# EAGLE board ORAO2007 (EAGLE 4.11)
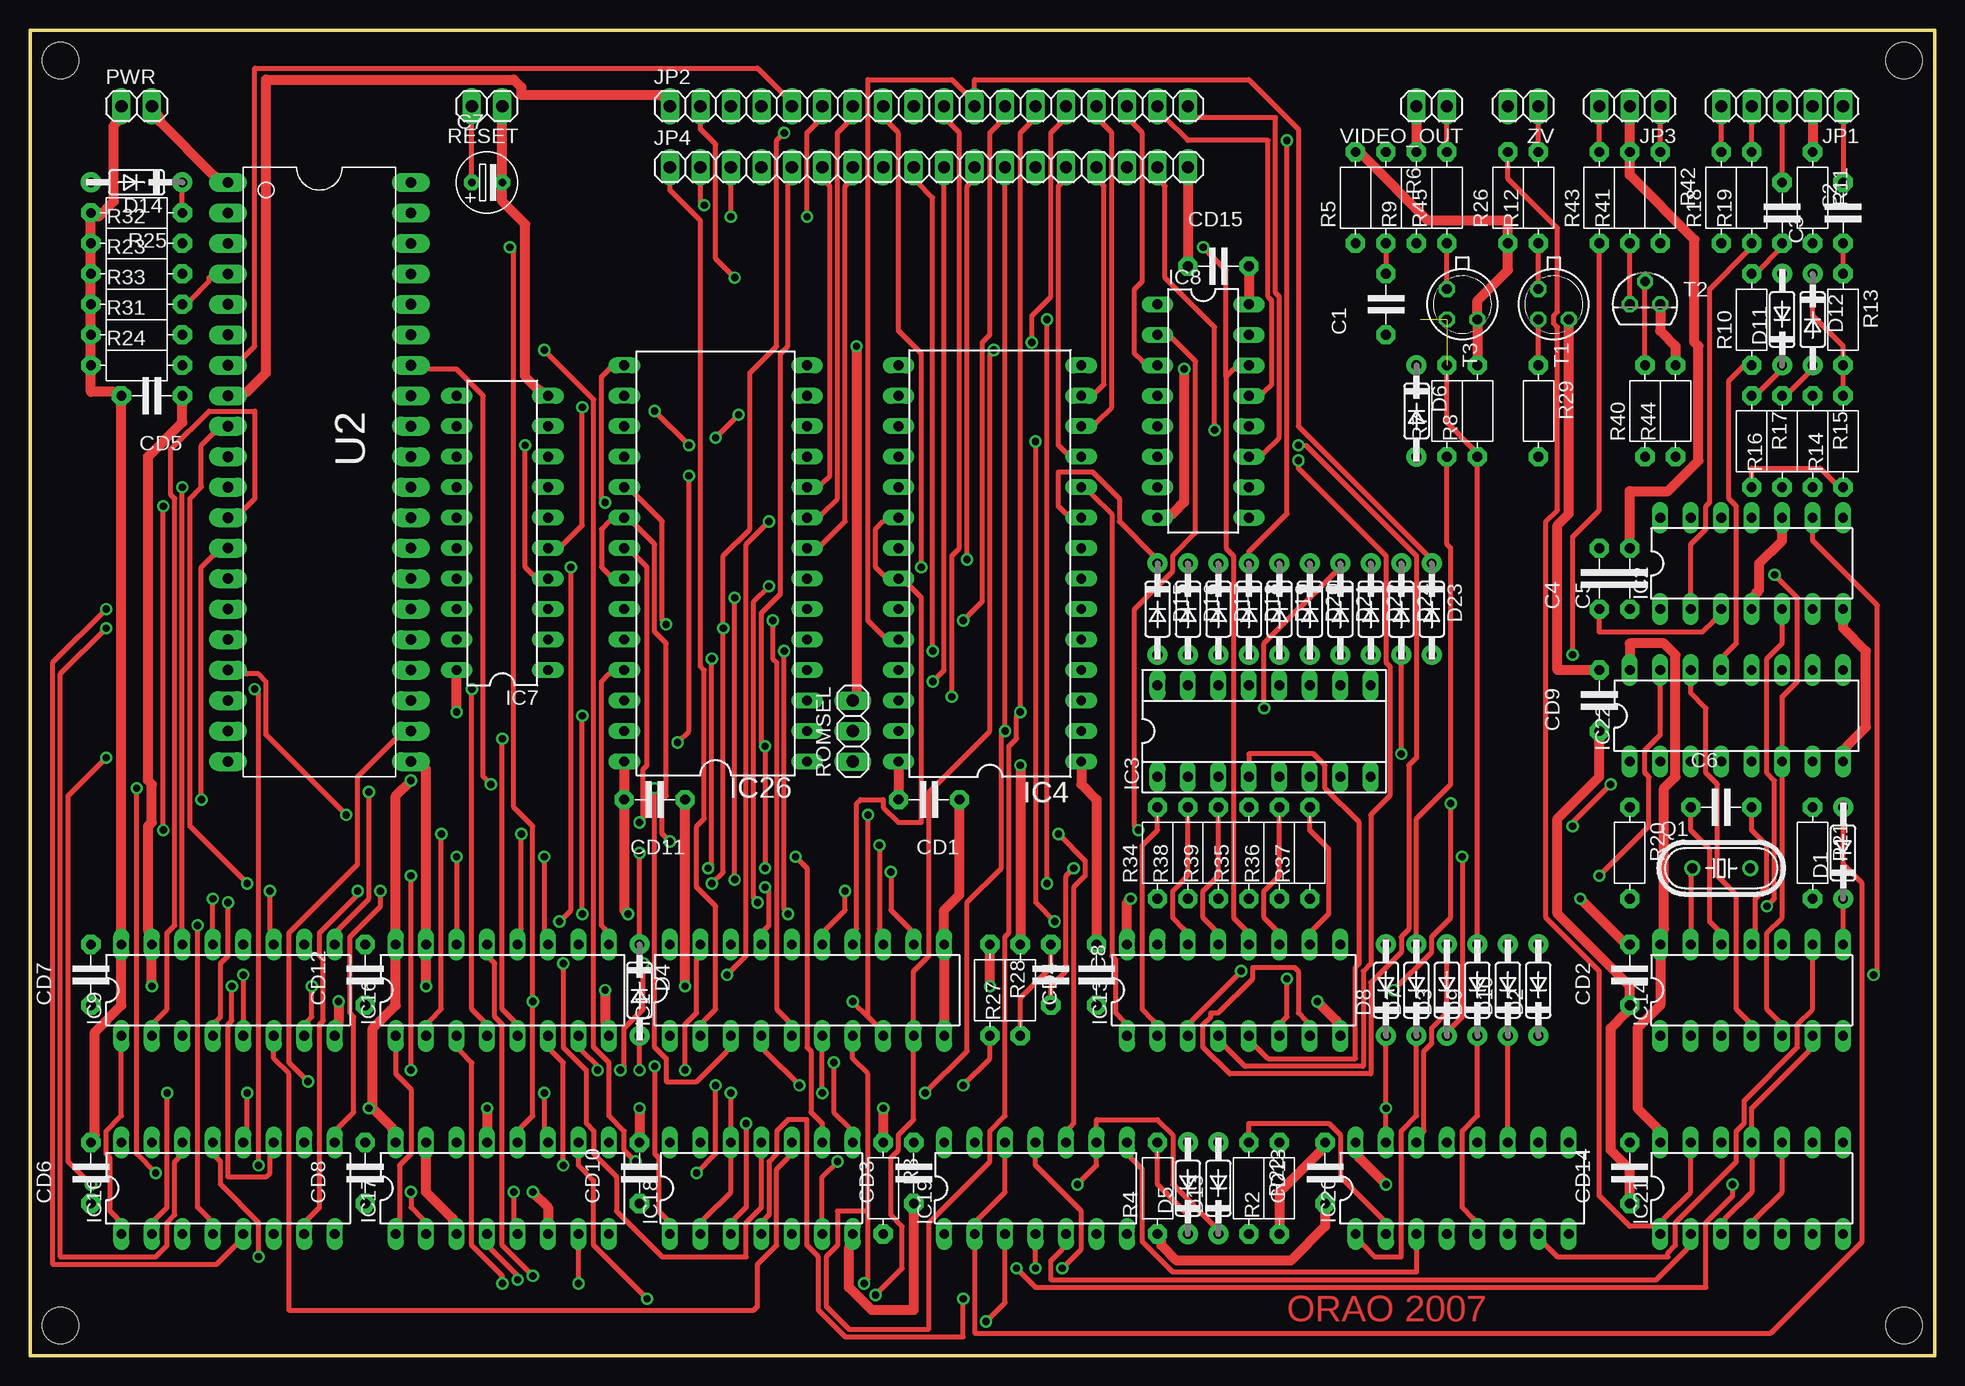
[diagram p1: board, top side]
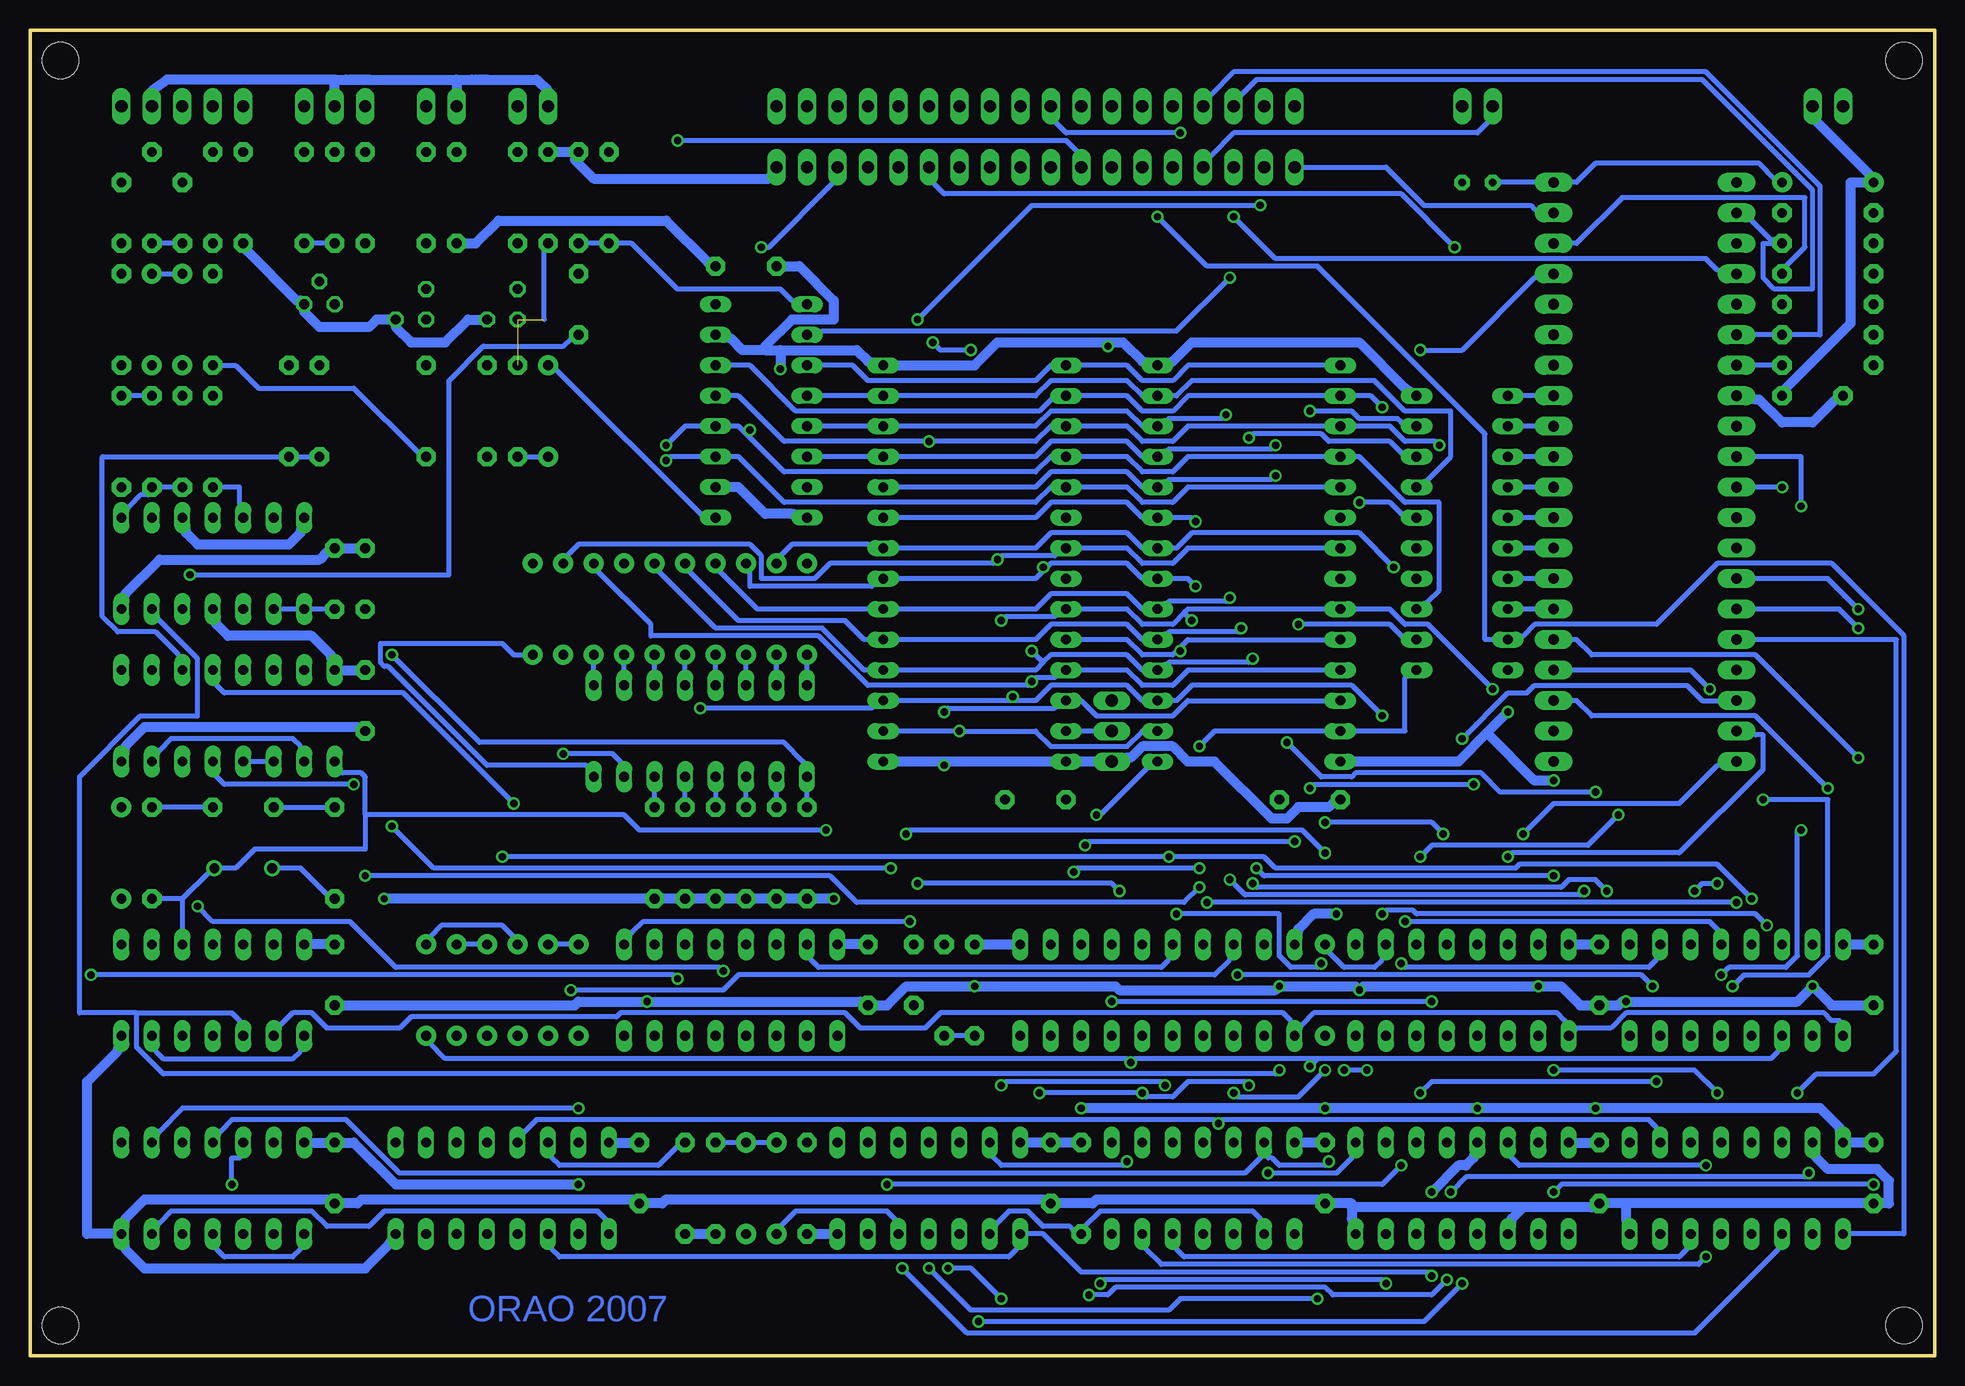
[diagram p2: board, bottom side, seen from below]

Size 158.75 x 110.49 mm. Coordinates in mm from the lower left corner, seen from the top.
Outline: 0,0 158.75,0 158.75,110.49 0,110.49 0,0
Copper layers (1*16): Top 0.035mm / dielectric 1.5mm / Bottom 0.035mm
Design rules "default": minimum track width 16mil, minimum drill 24mil, track to track 8mil, track to pad 8mil, pad to pad 8mil, via to via 8mil, smd to smd 8mil, copper to edge 40mil, drill to drill 8mil, minimum pad ring 10mil, minimum via ring 8mil, stop-mask expansion 4mil, vias tented up to drill 0mil, thermal gap 10mil
Net classes: 0 default: width 0.406 mm, drill 0.203 mm; 1 gnd: width 0.813 mm, drill 0.203 mm; 2 vcc: width 0.813 mm, drill 0.203 mm
Holes 3.05 mm at 2.54,107.95 156.21,107.95 156.21,2.54 2.54,2.54

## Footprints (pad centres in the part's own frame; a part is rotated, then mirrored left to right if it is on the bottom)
C-5 = drill 0.813 pad 1.6 octagon: 1 -2.54,0; 2 2.54,0
ES-2,5L = drill 0.61 pad 1.27 octagon: 1 0,0; 2 2.54,0
DO35-10 = drill 0.813 pad 1.676 round: A 3.81,0; C -3.81,0
DIL20 = drill 0.813 long: 1 -11.43,-3.81; 2 -8.89,-3.81; 3 -6.35,-3.81; 4 -3.81,-3.81; 5 -1.27,-3.81; 6 1.27,-3.81; 7 3.81,-3.81; 8 6.35,-3.81; 9 8.89,-3.81; 10 11.43,-3.81; 11 11.43,3.81; 12 8.89,3.81; 13 6.35,3.81; 14 3.81,3.81; 15 1.27,3.81; 16 -1.27,3.81; 17 -3.81,3.81; 18 -6.35,3.81; 19 -8.89,3.81; 20 -11.43,3.81
DIL14 = drill 0.813 long: 1 -7.62,-3.81; 2 -5.08,-3.81; 3 -2.54,-3.81; 4 0,-3.81; 5 2.54,-3.81; 6 5.08,-3.81; 7 7.62,-3.81; 8 7.62,3.81; 9 5.08,3.81; 10 2.54,3.81; 11 0,3.81; 12 -2.54,3.81; 13 -5.08,3.81; 14 -7.62,3.81
SOCKED-16 = drill 0.813 long: 1 -8.89,-3.81; 2 -6.35,-3.81; 3 -3.81,-3.81; 4 -1.27,-3.81; 5 1.27,-3.81; 6 3.81,-3.81; 7 6.35,-3.81; 8 8.89,-3.81; 9 8.89,3.81; 10 6.35,3.81; 11 3.81,3.81; 12 1.27,3.81; 13 -1.27,3.81; 14 -3.81,3.81; 15 -6.35,3.81; 16 -8.89,3.81
DIL28 = drill 0.813 long: 1 -16.51,-7.62; 2 -13.97,-7.62; 3 -11.43,-7.62; 4 -8.89,-7.62; 5 -6.35,-7.62; 6 -3.81,-7.62; 7 -1.27,-7.62; 8 1.27,-7.62; 9 3.81,-7.62; 10 6.35,-7.62; 11 8.89,-7.62; 12 11.43,-7.62; 13 13.97,-7.62; 14 16.51,-7.62; 15 16.51,7.62; 16 13.97,7.62; 17 11.43,7.62; 18 8.89,7.62; 19 6.35,7.62; 20 3.81,7.62; 21 1.27,7.62; 22 -1.27,7.62; 23 -3.81,7.62; 24 -6.35,7.62; 25 -8.89,7.62; 26 -11.43,7.62; 27 -13.97,7.62; 28 -16.51,7.62
DIL16 = drill 0.813 long: 1 -8.89,-3.81; 2 -6.35,-3.81; 3 -3.81,-3.81; 4 -1.27,-3.81; 5 1.27,-3.81; 6 3.81,-3.81; 7 6.35,-3.81; 8 8.89,-3.81; 9 8.89,3.81; 10 6.35,3.81; 11 3.81,3.81; 12 1.27,3.81; 13 -1.27,3.81; 14 -3.81,3.81; 15 -6.35,3.81; 16 -8.89,3.81
DIL28-6 = drill 0.813 long: 1 -16.51,-7.62; 2 -13.97,-7.62; 3 -11.43,-7.62; 4 -8.89,-7.62; 5 -6.35,-7.62; 6 -3.81,-7.62; 7 -1.27,-7.62; 8 1.27,-7.62; 9 3.81,-7.62; 10 6.35,-7.62; 11 8.89,-7.62; 12 11.43,-7.62; 13 13.97,-7.62; 14 16.51,-7.62; 15 16.51,7.62; 16 13.97,7.62; 17 11.43,7.62; 18 8.89,7.62; 19 6.35,7.62; 20 3.81,7.62; 21 1.27,7.62; 22 -1.27,7.62; 23 -3.81,7.62; 24 -6.35,7.62; 25 -8.89,7.62; 26 -11.43,7.62; 27 -13.97,7.62; 28 -16.51,7.62
1X05 = drill 1.016 long: 1 -5.08,0; 2 -2.54,0; 3 0,0; 4 2.54,0; 5 5.08,0
1X18 = drill 1.016 long: 1 -21.59,0; 2 -19.05,0; 3 -16.51,0; 4 -13.97,0; 5 -11.43,0; 6 -8.89,0; 7 -6.35,0; 8 -3.81,0; 9 -1.27,0; 10 1.27,0; 11 3.81,0; 12 6.35,0; 13 8.89,0; 14 11.43,0; 15 13.97,0; 16 16.51,0; 17 19.05,0; 18 21.59,0
1X03 = drill 1.016 long: 1 -2.54,0; 2 0,0; 3 2.54,0
1X02 = drill 1.016 long: 1 -1.27,0; 2 1.27,0
HC49/S = drill 0.813 round: 1 -2.413,0; 2 2.413,0
R-7,5 = drill 0.813 pad 1.6 octagon: 1 -3.81,0; 2 3.81,0
TO18 = drill 0.813 octagon: 1 -1.27,-1.27; 2 1.27,-1.27; 3 1.27,1.27
TO92 = drill 0.813 octagon: 1 1.27,0; 2 0,1.905; 3 -1.27,0
DIP-40 = drill 0.889 pad 1.6 long: 1 -22.86,-7.62; 2 -20.32,-7.62; 3 -17.78,-7.62; 4 -15.24,-7.62; 5 -12.7,-7.62; 6 -10.16,-7.62; 7 -7.62,-7.62; 8 -5.08,-7.62; 9 -2.54,-7.62; 10 0,-7.62; 11 2.54,-7.62; 12 5.08,-7.62; 13 7.62,-7.62; 14 10.16,-7.62; 15 12.7,-7.62; 16 15.24,-7.62; 17 17.78,-7.62; 18 20.32,-7.62; 19 22.86,-7.62; 20 25.4,-7.62; 21 25.4,7.62; 22 22.86,7.62; 23 20.32,7.62; 24 17.78,7.62; 25 15.24,7.62; 26 12.7,7.62; 27 10.16,7.62; 28 7.62,7.62; 29 5.08,7.62; 30 2.54,7.62; 31 0,7.62; 32 -2.54,7.62; 33 -5.08,7.62; 34 -7.62,7.62; 35 -10.16,7.62; 36 -12.7,7.62; 37 -15.24,7.62; 38 -17.78,7.62; 39 -20.32,7.62; 40 -22.86,7.62

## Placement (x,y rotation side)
C1  100p  [C-5]  113.03,87.63 90 top
C2  [C-5]  146.05,95.25 270 top
C3  100n  [C-5]  151.13,95.25 90 top
C4  22n  [C-5]  130.81,64.77 90 top
C5  10n  [C-5]  133.35,64.77 90 top
C6  1n  [C-5]  140.97,45.72 0 top
C7  10u  [ES-2,5L]  36.83,97.79 0 top
C8  100p  [C-5]  85.09,31.75 270 top
CD1  100n  [C-5]  74.93,46.35 180 top
CD2  100n  [C-5]  133.35,31.75 90 top
CD3  100n  [C-5]  73.66,15.24 90 top
CD4  100n  [C-5]  88.9,31.75 90 top
CD5  100n  [C-5]  10.16,80.01 180 top
CD6  100n  [C-5]  5.08,15.24 90 top
CD7  100n  [C-5]  5.08,31.75 90 top
CD8  100n  [C-5]  27.94,15.24 90 top
CD9  100n  [C-5]  130.81,54.61 90 top
CD10  100n  [C-5]  50.8,15.24 90 top
CD11  100n  [C-5]  52.07,46.35 180 top
CD12  100n  [C-5]  27.94,31.75 90 top
CD13  100n  [C-5]  107.95,15.24 90 top
CD14  100n  [C-5]  133.35,15.24 90 top
CD15  100n  [C-5]  99.06,90.81 0 top
D1  1N4148  [DO35-10]  151.13,41.91 90 top
D2  1N4148  [DO35-10]  125.73,30.48 90 top
D3  1N4148  [DO35-10]  118.11,30.48 90 top
D4  1N4148  [DO35-10]  50.8,30.48 270 top
D5  1N4148  [DO35-10]  96.52,13.97 90 top
D6  1N4148  [DO35-10]  115.57,78.74 270 top
D7  1N4148  [DO35-10]  115.57,30.48 90 top
D8  1N4148  [DO35-10]  113.03,30.48 90 top
D9  1N4148  [DO35-10]  120.65,30.48 90 top
D10  1N4148  [DO35-10]  123.19,30.48 90 top
D11  1N4148  [DO35-10]  146.05,86.36 90 top
D12  1N4148  [DO35-10]  148.59,86.36 270 top
D13  1N4148  [DO35-10]  99.06,13.97 90 top
D14  1N4148  [DO35-10]  8.89,97.79 180 top
D15  1N4148  [DO35-10]  93.98,62.23 270 top
D16  1N4148  [DO35-10]  96.52,62.23 270 top
D17  1N4148  [DO35-10]  99.06,62.23 270 top
D18  1N4148  [DO35-10]  101.6,62.23 270 top
D19  1N4148  [DO35-10]  104.14,62.23 270 top
D20  1N4148  [DO35-10]  106.68,62.23 270 top
D21  1N4148  [DO35-10]  109.22,62.23 270 top
D22  1N4148  [DO35-10]  111.76,62.23 270 top
D23  1N4148  [DO35-10]  116.84,62.23 270 top
D24  1N4148  [DO35-10]  114.3,62.23 270 top
IC1  GAL16V8  [DIL20]  64.77,30.48 0 top
IC2  NE556N  [DIL14]  143.51,66.04 0 top
IC3  [SOCKED-16]  102.87,52.07 0 top
IC4  27256  [DIL28]  80.01,66.04 90 top
IC7  74AC245N  [DIL20]  39.37,68.58 90 top
IC8  74HC165N  [DIL16]  97.79,78.74 270 top
IC9  74AC257N  [DIL16]  16.51,30.48 0 top
IC10  74AC257N  [DIL16]  16.51,13.97 0 top
IC13  74AC257N  [DIL16]  100.33,30.48 0 top
IC14  74AC04N  [DIL14]  143.51,30.48 0 top
IC16  74AC257N  [DIL16]  39.37,30.48 0 top
IC17  74AC257N  [DIL16]  39.37,13.97 0 top
IC18  74AC393N  [DIL14]  60.96,13.97 0 top
IC19  74AC393N  [DIL14]  83.82,13.97 0 top
IC20  74AC139N  [DIL16]  119.38,13.97 0 top
IC21  74AC74N  [DIL14]  143.51,13.97 0 top
IC22  74AC390N  [DIL16]  142.24,53.34 0 top
IC26  [DIL28-6]  57.15,66.04 90 top
JP1  [1X05]  146.05,104.14 180 top
JP2  [1X18]  74.93,104.14 0 top
JP3  [1X03]  133.35,104.14 180 top
JP4  [1X18]  74.93,99.06 0 top
PWR  [1X02]  8.89,104.14 0 top
Q1  8MHz  [HC49/S]  140.97,40.64 0 top
R2  10K  [R-7,5]  104.14,13.97 90 top
R3  10K  [R-7,5]  71.12,13.97 270 top
R4  470  [R-7,5]  93.98,13.97 90 top
R5  1K  [R-7,5]  110.49,96.52 90 top
R6  1K5  [R-7,5]  113.03,96.52 270 top
R7  330  [R-7,5]  118.11,78.74 90 top
R8  1K  [R-7,5]  120.65,78.74 90 top
R9  4K7  [R-7,5]  115.57,96.52 90 top
R10  47K  [R-7,5]  143.51,86.36 90 top
R11  470  [R-7,5]  148.59,96.52 270 top
R12  47  [R-7,5]  125.73,96.52 90 top
R13  10K  [R-7,5]  151.13,86.36 270 top
R14  22K  [R-7,5]  151.13,76.2 90 top
R15  22K  [R-7,5]  148.59,76.2 270 top
R16  47K  [R-7,5]  146.05,76.2 90 top
R17  47K  [R-7,5]  143.51,76.2 270 top
R18  100  [R-7,5]  140.97,96.52 90 top
R19  100  [R-7,5]  143.51,96.52 90 top
R20  330  [R-7,5]  133.35,41.91 270 top
R21  330  [R-7,5]  148.59,41.91 270 top
R22  10K  [R-7,5]  101.6,13.97 270 top
R23  10K  [R-7,5]  8.89,90.17 0 top
R24  10K  [R-7,5]  8.89,82.55 0 top
R25  10K  [R-7,5]  8.89,95.25 180 top
R26  10K  [R-7,5]  123.19,96.52 90 top
R27  1K  [R-7,5]  82.55,30.48 90 top
R28  1K  [R-7,5]  80.01,30.48 270 top
R29  1K  [R-7,5]  125.73,78.74 270 top
R31  10K  [R-7,5]  8.89,85.09 0 top
R32  10K  [R-7,5]  8.89,92.71 0 top
R33  10K  [R-7,5]  8.89,87.63 0 top
R34  10K  [R-7,5]  93.98,41.91 90 top
R35  10K  [R-7,5]  101.6,41.91 90 top
R36  10K  [R-7,5]  104.14,41.91 90 top
R37  10K  [R-7,5]  106.68,41.91 90 top
R38  10K  [R-7,5]  96.52,41.91 90 top
R39  10K  [R-7,5]  99.06,41.91 90 top
R40  10K  [R-7,5]  134.62,78.74 90 top
R41  10K  [R-7,5]  133.35,96.52 90 top
R42  470  [R-7,5]  135.89,96.52 270 top
R43  1K2  [R-7,5]  130.81,96.52 90 top
R44  4K7  [R-7,5]  137.16,78.74 90 top
R45  47  [R-7,5]  118.11,96.52 90 top
RESET  [1X02]  38.1,104.14 180 top
ROMSEL  [1X03]  68.58,52.07 90 top
T1  BC108C  [TO18]  127,87.63 270 top
T2  BC214  [TO92]  134.62,87.63 0 top
T3  BC108C  [TO18]  119.38,87.63 270 top
U2  [DIP-40]  24.13,74.93 270 top
VIDEO_OUT  [1X02]  116.84,104.14 180 top
ZV  [1X02]  124.46,104.14 180 top

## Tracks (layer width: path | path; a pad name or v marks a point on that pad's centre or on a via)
1B9  (via drill 0.61)
  Top 0.406: v52.07,24.13 52.07,16.83 52.39,16.51 52.39,12.06 53.02,11.43 IC18.1 | v66.99,24.45 66.99,20.32 68.26,19.05 IC18.8
  Bottom 0.406: 51.44,24.77 v52.07,24.13 | 51.44,24.77 13.65,24.77 13.02,25.4 IC9.3 | 51.44,24.77 66.67,24.77 v66.99,24.45 67.31,24.77 124.14,24.77 125.41,26.04 D2.C
1B10  (via drill 0.61)
  Top 0.406: v86.04,7.3 87.63,8.89 87.63,12.06 83.82,15.88 IC19.11
  Bottom 0.406: v86.04,7.3 80.64,1.91 20,1.91 13.02,8.89 IC10.3
1B16  (via drill 0.61)
  Top 0.406: v39.37,6.03 39.37,6.67 36.83,9.21 36.83,24.45 35.88,25.4 IC16.3 | v79.69,2.86 81.28,4.45 IC19.3
  Bottom 0.406: v39.37,6.03 42.55,2.86 v79.69,2.86
2B10
  Bottom 0.406: IC10.6 20.64,8.89 21.27,8.26 62.55,8.26 63.18,8.89 IC18.5
2B16  (via drill 0.61)
  Top 0.406: v44.45,15.88 44.45,24.45 43.5,25.4 IC16.6 | v87.31,14.29 88.9,15.88 IC19.9 88.9,19.68 93.98,19.68 95.25,18.41 95.25,14.29 98.74,10.79 D13.C
  Bottom 0.406: v44.45,15.88 46.04,14.29 v87.31,14.29
2MHZ  (via drill 0.61)
  Top 0.406: v131.76,47.62 128.59,44.45 v128.59,44.13 | v87,40.64 86.36,40.01 86.36,32.07 85.09,30.8 C8.2
  Bottom 0.406: v131.76,47.62 142.56,47.62 143.19,48.26 IC22.5 | v128.59,44.13 125.09,40.64 v87,40.64
2MHZ'  (via drill 0.61)
  Top 0.406: v64.14,22.54 61.28,25.4 IC1.4 | v77.79,22.54 80.01,24.77 R28.2 | C8.1 85.09,32.38 82.55,29.84 R27.1
  Bottom 0.406: v64.14,22.54 64.45,22.86 77.47,22.86 v77.79,22.54 | R28.2 R27.1
2Y0
  Bottom 0.406: IC1.16 63.82,33.02 64.45,32.38 93.03,32.38 93.66,33.02 IC13.15
2Y1  (via drill 0.61)
  Top 0.406: v61.28,39.05 61.59,38.73 61.59,35.88 61.28,35.56 IC1.17 | v130.81,40.01 134.94,44.13 134.94,48.26 134.62,48.58 134.62,50.48 135.89,51.75 IC22.15
  Bottom 0.406: v61.28,39.05 62.55,37.78 89.85,37.78 92.08,40.01 v130.81,40.01
2Y2  (via drill 0.61)
  Top 0.406: v113.67,30.48 116.84,33.66 116.84,34.92 118.43,36.51 v118.43,46.04
  Bottom 0.406: v113.67,30.48 100.97,30.48 99.69,31.75 60.01,31.75 58.74,33.02 IC1.18 | v118.43,46.04 127.64,55.24 142.56,55.24 143.19,55.88 IC22.12
2Y3  (via drill 0.61)
  Top 0.406: v54.61,23.81 54.61,27.62 55.56,28.57 55.56,33.02 IC1.19
  Bottom 0.406: v54.61,23.81 54.93,23.5 147.64,23.5 149.86,25.72 149.86,28.57 | 149.86,28.57 141.92,28.57 141.29,27.94 IC14.3 | 149.86,28.57 154.62,28.57 154.62,48.26 149.54,53.34 144.78,53.34 144.78,58.1 147.96,61.28 IC2.6
3B9  (via drill 0.61)
  Top 0.406: v44.45,32.7 44.45,25.72 46.35,23.81 46.35,19.37 46.99,18.73 46.99,16.83 48.9,14.92 48.9,12.06 52.7,8.26 59.69,8.26 59.69,11.11 60.96,12.38 IC18.11
  Bottom 0.406: v44.45,32.7 44.13,32.38 23.81,32.38 23.18,33.02 IC9.10
3B10  (via drill 0.61)
  Top 0.406: v59.69,19.37 59.69,12.38 58.74,11.43 IC18.3
  Bottom 0.406: IC10.10 23.18,19.05 23.81,19.68 59.37,19.68 v59.69,19.37 60.01,19.68 116.52,19.68 117.47,18.73 IC20.13
3B16  (via drill 0.61)
  Top 0.406: v85.72,43.5 87.95,41.27 87.95,40.01 87,39.05 87,19.37 86.68,19.05 IC19.10 | D4.C v50.8,41.91
  Bottom 0.406: v85.72,43.5 85.41,43.81 52.7,43.81 v50.8,41.91 | IC16.10 46.04,33.02 46.67,32.38 49.21,32.38 50.48,33.66 D4.C
3B17  (via drill 0.61)
  Top 0.406: v51.44,4.76 46.99,9.21 46.99,14.61 45.72,15.88 IC17.10 | v83.82,7.3 IC19.4
  Bottom 0.406: v83.82,7.3 80.33,3.81 63.82,3.81 62.87,4.76 v51.44,4.76
4B9  (via drill 0.61)
  Top 0.406: v63.82,41.59 64.77,40.64 64.77,25.72 65.09,25.4 65.09,20.32 66.04,19.37 IC18.9 | IC9.13 v15.24,38.1 | v119.38,41.59 119.38,28.26 118.43,27.3 D3.C
  Bottom 0.406: v15.24,38.1 18.1,40.96 34.61,40.96 34.92,40.64 54.93,40.64 55.88,41.59 v63.82,41.59 v119.38,41.59
4B10  (via drill 0.61)
  Top 0.406: v19.05,8.26 19.05,11.11 15.88,14.29 15.88,16.19 15.56,16.51 IC10.13 | v67.31,16.19 66.04,14.92 IC18.6
  Bottom 0.406: v19.05,8.26 19.68,7.62 64.45,7.62 65.72,8.89 IC18.6 | v67.31,16.19 67.63,15.88 77.79,15.88 78.42,16.51 IC19.13
4B16  (via drill 0.61)
  Top 0.406: v41.91,6.67 39.37,9.21 39.37,27.62 38.73,28.26 38.73,32.7 38.42,33.02 IC16.13 | IC19.8 91.76,16.51 92.71,15.56 92.71,9.53 95.25,6.99 115.57,6.99 IC20.3
  Bottom 0.406: IC20.3 115.25,8.89 114.62,8.26 77.15,8.26 76.52,8.89 IC19.1 74.3,10.16 71.12,6.99 42.23,6.99 v41.91,6.67
8MHZ  (via drill 0.61)
  Top 0.406: v58.74,89.85 57.15,91.44 57.15,100.97 55.88,102.23 JP2.2 | v92.39,43.81 92.08,44.13 92.08,62.23 95.25,65.41 95.25,66.67 97.16,68.58 97.16,82.87 95.25,84.77 IC8.2
  Bottom 0.406: 146.05,38.1 143.83,40.32 Q1.2 141.6,40.64 140.02,42.23 130.81,42.23 130.81,45.09 | 146.05,38.1 R21.2 | 130.81,45.09 130.81,48.26 131.13,48.58 132.72,48.58 IC22.1 | 146.05,38.1 IC14.10 | v58.74,89.85 63.18,85.41 92.71,85.41 IC8.2 | 130.81,45.09 109.22,45.09 107.95,43.81 v92.39,43.81
A0  (via drill 0.61)
  Top 0.406: v28.26,46.99 28.26,38.1 25.72,35.56 IC9.9 | v53.98,51.12 54.93,52.07 v54.93,73.34 | IC13.1 91.12,27.94 90.49,28.57 90.49,33.02 90.17,33.34 90.17,70.17 88.58,71.75 IC4.10 | JP4.6 66.36,97.79 66.67,97.47 66.67,73.34 66.04,72.71 IC26.10
  Bottom 0.406: IC4.10 74.93,72.39 73.66,73.66 67.31,73.66 66.04,72.39 IC26.10 63.82,73.03 55.24,73.03 v54.93,73.34 | v28.26,46.99 36.2,46.99 37.78,48.58 48.26,48.58 48.58,48.26 51.12,48.26 v53.98,51.12
A0'  (via drill 0.61)
  Top 0.406: v20,38.73 20,35.56 IC9.11 | v18.1,39.37 13.34,44.13 13.34,71.44 14.29,72.39 14.29,75.88 15.24,76.83 U2.9
  Bottom 0.406: v20,38.73 19.37,39.37 v18.1,39.37
A1  (via drill 0.61)
  Top 0.406: v23.5,30.8 23.5,28.26 23.18,27.94 IC9.7 | v58.1,31.75 59.69,33.34 59.69,67.63 v61.59,69.53 | JP2.7 68.26,102.87 67.31,101.92 67.31,71.44 66.04,70.17 IC26.9 | D15.C 93.66,66.67 90.81,69.53 90.81,71.44 88.58,73.66 85.72,73.66 85.72,70.8 86.36,70.17 IC4.9
  Bottom 0.406: IC4.9 74.93,69.85 73.66,71.12 67.31,71.12 66.04,69.85 IC26.9 61.91,69.85 v61.59,69.53 | v23.5,30.8 24.45,31.75 v58.1,31.75
A1'  (via drill 0.61)
  Top 0.406: v11.11,43.81 v11.11,70.8 | v17.78,31.75 IC9.5
  Bottom 0.406: v17.78,31.75 17.14,32.38 12.38,32.38 11.43,33.34 11.43,43.81 v11.11,43.81 | v11.11,70.8 11.11,74.93 U2.10
A2  (via drill 0.61)
  Top 0.406: v44.13,36.2 45.09,37.15 v45.09,65.72 | JP4.7 68.26,97.79 67.94,97.47 67.94,69.53 66.04,67.63 IC26.8
  Bottom 0.406: v44.13,36.2 18.73,36.2 18.1,35.56 IC9.12 | v45.09,65.72 47.94,68.58 61.91,68.58 63.18,67.31 IC26.8 66.04,67.31 67.31,68.58 73.66,68.58 74.93,67.31 IC4.8 88.9,67.63 95.25,67.63 96.2,66.67 D16.C
A2'  (via drill 0.61)
  Top 0.406: IC9.14 v12.7,72.39
  Bottom 0.406: v12.7,72.39 U2.11
A3  (via drill 0.61)
  Top 0.406: v16.51,37.78 16.51,33.34 15.88,32.7 15.88,28.26 15.56,27.94 IC9.4 | v60.64,37.78 60.33,38.1 60.33,62.87 v61.59,64.14 | v74.3,65.72 74.3,83.5 72.39,85.41 72.39,101.92 71.44,102.87 JP2.8
  Bottom 0.406: 73.98,65.72 73.66,66.04 67.31,66.04 66.04,64.77 IC26.7 62.23,64.77 v61.59,64.14 | 73.98,65.72 74.93,64.77 IC4.7 88.58,64.14 98.74,64.14 98.74,65.41 D17.C | v16.51,37.78 v60.64,37.78 | 73.98,65.72 v74.3,65.72
A3'
  Top 0.406: IC9.2 10.48,27.94 11.43,28.89 11.43,35.24 12.06,35.88 12.06,71.44 11.75,71.75 11.75,75.56 14.92,78.74 18.73,78.74 18.73,71.44 17.78,70.48 U2.12
A4  (via drill 0.61)
  Top 0.406: v104.78,101.28 104.78,70.17 101.6,66.99 D18.C | v29.21,38.73 29.21,37.47 26.67,34.92 26.67,28.57 26.99,28.26 26.99,20.32 25.72,19.05 IC10.9 | v58.74,39.69 v58.74,63.18
  Bottom 0.406: v104.78,101.28 72.39,101.28 71.44,100.33 JP4.8 | v29.21,38.73 29.53,38.42 57.47,38.42 v58.74,39.69 | v58.74,63.18 59.05,62.87 63.82,62.87 IC26.6 66.04,62.23 67.31,63.5 73.66,63.5 74.93,62.23 IC4.6 98.11,62.23 101.28,65.41 D18.C
A4'  (via drill 0.61)
  Top 0.406: v16.83,30.8 16.83,27.94 16.51,27.62 16.51,14.92 19.68,14.92 20,15.24 20,16.51 IC10.11 | v14.29,46.35 14.29,65.72 15.24,66.67 U2.13
  Bottom 0.406: v16.83,30.8 15.88,31.75 10.48,31.75 8.89,33.34 8.89,46.35 v14.29,46.35
A5  (via drill 0.61)
  Top 0.406: v27.3,38.73 27.3,38.42 24.13,35.24 24.13,33.34 24.45,33.02 24.45,27.94 24.13,27.62 24.13,12.38 23.18,11.43 IC10.7 | v56.83,39.37 57.78,40.32 v57.78,60.64 57.78,66.67 60.01,68.9 60.01,81.92 62.23,84.14 62.23,101.28 v62.87,101.92
  Bottom 0.406: v27.3,38.73 28.26,39.69 30.48,39.69 31.11,39.05 56.52,39.05 v56.83,39.37 | v57.78,60.64 58.1,60.33 63.82,60.33 IC26.5 66.04,59.69 67.31,60.96 73.66,60.96 74.93,59.69 IC4.5 89.22,59.69 90.81,61.28 99.69,61.28 103.82,65.41 D19.C | v62.87,101.92 72.39,101.92 73.34,102.87 JP2.9
A5'  (via drill 0.61)
  Top 0.406: v6.35,62.23 1.91,57.78 1.91,7.62 15.56,7.62 17.14,9.21 IC10.5
  Bottom 0.406: v6.35,62.23 8.89,64.77 U2.14
A6  (via drill 0.61)
  Top 0.406: v18.1,21.91 18.1,19.05 IC10.12 | v31.75,23.81 v31.75,40.01 | v56.52,40.64 56.83,40.96 v56.83,58.1 | v75.25,58.74 75.25,96.52 73.98,97.79 JP4.9
  Bottom 0.406: 74.3,57.78 73.66,58.42 67.31,58.42 66.04,57.15 IC26.4 63.82,57.78 57.15,57.78 v56.83,58.1 | 74.3,57.78 74.93,57.15 IC4.4 89.22,57.15 92.71,60.64 101.6,60.64 106.36,65.41 D20.C | v18.1,21.91 20,23.81 v31.75,23.81 | v31.75,40.01 55.88,40.01 v56.52,40.64 | 74.3,57.78 v75.25,58.74
A6'  (via drill 0.61)
  Top 0.406: v6.35,60.64 2.54,56.83 2.54,8.26 10.48,8.26 11.43,9.21 11.43,11.11 12.06,11.75 12.06,16.19 12.38,16.51 IC10.14
  Bottom 0.406: v6.35,60.64 7.94,62.23 U2.15
A7  (via drill 0.61)
  Top 0.406: v13.97,35.88 13.97,12.38 14.92,11.43 IC10.4 | v46.04,36.83 v46.04,53.34 | v76.83,54.93 76.83,66.67 77.47,67.31 77.47,101.92 76.52,102.87 JP2.10 | v102.87,53.98 102.87,59.37 108.9,65.41 D21.C
  Bottom 0.406: 76.83,54.61 74.93,54.61 73.66,55.88 67.31,55.88 66.04,54.61 IC26.3 63.18,54.61 61.91,55.88 48.58,55.88 v46.04,53.34 | 76.83,54.61 IC4.3 88.58,53.98 v102.87,53.98 | v13.97,35.88 14.92,36.83 43.18,36.83 43.5,37.15 45.72,37.15 v46.04,36.83 | 76.83,54.61 v76.83,54.93
A7'  (via drill 0.61)
  Top 0.406: v11.43,21.91 11.43,12.38 10.48,11.43 IC10.2
  Bottom 0.406: v11.43,21.91 9.84,23.5 5.08,23.5 3.17,25.4 3.17,59.69 U2.16
A8  (via drill 0.61)
  Top 0.406: IC16.9 47.94,35.56 47.62,35.88 47.62,56.2 48.26,56.83 IC26.25 | v75.25,56.2 76.2,57.15 JP4.10
  Bottom 0.406: IC26.25 62.23,57.15 63.5,55.88 66.04,55.88 67.31,57.15 IC4.25 73.34,56.52 74.93,56.52 v75.25,56.2 75.56,55.88 88.9,55.88 93.03,60.01 107,60.01 107,60.96 111.44,65.41 D22.C
A8'  (via drill 0.61)
  Top 0.406: v42.86,41.59 42.86,35.56 IC16.11 | v26.35,45.09 19.68,51.75 19.68,56.2 19.05,56.83 18.1,56.83 U2.17
  Bottom 0.406: v42.86,41.59 41.91,42.55 28.89,42.55 v26.35,45.09
A9  (via drill 0.61)
  Top 0.406: v47.31,23.81 47.31,24.13 46.04,25.4 IC16.7 | v49.21,23.81 49.53,24.13 49.53,27.3 51.12,28.89 v51.12,32.7 | v63.18,36.83 62.87,37.15 v62.87,58.74 | IC4.24 71.12,60.01 69.85,61.28 69.85,106.36 76.83,106.36 78.11,105.09 JP2.11 78.74,106.36 101.6,106.36 105.73,102.23 105.73,77.47 116.52,66.67 D23.C
  Bottom 0.406: IC26.24 62.23,59.69 62.87,59.05 | 62.87,59.05 63.5,58.42 66.04,58.42 67.31,59.69 IC4.24 | v47.31,23.81 v49.21,23.81 | v51.12,32.7 51.44,32.38 53.66,32.38 54.61,33.34 54.61,36.83 v63.18,36.83 | v62.87,58.74 62.87,59.05
A9'  (via drill 0.61)
  Top 0.406: v39.37,51.44 39.37,28.89 40.32,27.94 IC16.5
  Bottom 0.406: v39.37,51.44 35.56,55.24 33.97,55.24 33.34,55.88 20.64,55.88 19.37,54.61 U2.18
A10  (via drill 0.61)
  Top 0.406: v40.96,43.5 40.96,35.56 IC16.12 | v50.8,44.45 51.12,44.77 51.12,48.9 51.44,49.21 51.44,65.72 50.48,66.67 IC26.21 | v78.11,66.36 78.11,97.47 78.42,97.79 JP4.11
  Bottom 0.406: IC26.21 62.23,67.31 63.5,66.04 66.04,66.04 67.31,67.31 IC4.21 73.34,66.67 77.79,66.67 v78.11,66.36 78.42,66.04 92.08,66.04 93.34,64.77 97.79,64.77 97.79,66.67 98.74,67.63 113.03,67.63 113.98,66.67 D24.C | v40.96,43.5 41.91,44.45 v50.8,44.45
A10'  (via drill 0.61)
  Top 0.406: v35.56,41.59 IC16.14
  Bottom 0.406: v35.56,41.59 35.24,41.91 21.27,41.91 14.29,48.9 14.29,51.75 14.92,51.75 U2.19
A11  (via drill 0.61)
  Top 0.406: v36.83,55.56 36.83,28.89 37.78,27.94 IC16.4 | v61.91,61.28 61.91,58.1 62.23,57.78 62.23,28.89 63.18,27.94 IC1.5 | v77.79,61.28 79.38,62.87 79.38,84.45 80.01,85.09 80.01,101.92 80.96,102.87 JP2.12
  Bottom 0.406: 62.55,61.91 62.23,62.23 IC26.23 45.4,62.23 44.13,60.96 42.23,60.96 v36.83,55.56 | 62.55,61.91 63.5,60.96 66.04,60.96 67.31,62.23 IC4.23 73.34,61.59 77.47,61.59 v77.79,61.28 | 62.55,61.91 v61.91,61.28
A11'  (via drill 0.61)
  Top 0.406: v34.29,43.5 34.29,28.89 33.34,27.94 IC16.2
  Bottom 0.406: v34.29,43.5 31.75,46.04 21.27,46.04 18.1,49.21 U2.20
A12  (via drill 0.61)
  Top 0.406: v55.56,15.24 57.15,16.83 v57.15,22.54 | v66.04,21.91 IC1.6 | JP4.12 v81.28,52.07 80.96,51.75 80.96,40.64 78.11,37.78 78.11,25.4 v74.61,21.91
  Bottom 0.406: IC26.2 66.04,52.07 67.31,50.8 73.66,50.8 74.93,52.07 v81.28,52.07 IC4.2 | v55.56,15.24 49.85,15.24 48.58,16.51 IC17.9 | v57.15,22.54 57.47,22.86 62.23,22.86 63.5,21.59 65.72,21.59 v66.04,21.91 v74.61,21.91
A12'  (via drill 0.61)
  Top 0.406: v42.86,21.91 42.86,19.05 IC17.11 | v23.18,22.86 21.59,24.45 21.59,35.24 27.3,40.96 27.3,48.26 30.48,51.44 U2.22
  Bottom 0.406: v42.86,21.91 41.91,22.86 v23.18,22.86
A13  (via drill 0.61)
  Top 0.406: v69.53,6.03 69.85,6.35 69.85,12.06 | 69.85,12.06 69.85,23.5 68.58,24.77 IC1.7 | v45.72,6.03 IC17.7 | JP2.13 83.5,102.87 82.55,101.92 v82.55,53.66 82.23,53.34 82.23,51.44 81.6,50.8 81.6,35.24 81.28,34.92 81.28,20 80.01,18.73 80.01,16.19 74.93,11.11 74.93,2.22 68.26,2.22 66.36,4.13 66.36,8.26 67.31,9.21 67.31,12.06 69.85,12.06
  Bottom 0.406: IC26.26 62.23,54.61 63.5,53.34 69.85,53.34 71.12,54.61 IC4.26 73.34,53.98 82.23,53.98 v82.55,53.66 | v45.72,6.03 46.04,6.35 69.22,6.35 v69.53,6.03
A13'  (via drill 0.61)
  Top 0.406: v40.32,13.65 40.32,11.43 IC17.5 | v10.48,15.24 8.89,16.83 v8.89,47.31
  Bottom 0.406: v40.32,13.65 39.05,14.92 10.79,14.92 v10.48,15.24 | v8.89,47.31 14.92,53.34 28.57,53.34 29.84,54.61 U2.23
A14  (via drill 0.61)
  Top 0.406: 69.85,28.26 70.48,27.62 IC1.8 | v68.58,29.53 69.85,28.26 | IC17.12 40.96,19.05 41.91,20 v41.91,29.53 41.91,44.13 40.32,45.72 40.32,92.08 v40.01,92.39 | 69.85,28.26 v69.85,45.09
  Bottom 0.406: v41.91,29.53 v68.58,29.53 | v69.85,45.09 69.53,45.09 65.72,48.9 IC26.1 | v40.01,92.39 44.45,96.84 82.55,96.84 83.5,97.79 JP4.13
A14'  (via drill 0.61)
  Top 0.406: v19.05,15.88 19.05,55.24 v18.73,55.56
  Bottom 0.406: v19.05,15.88 34.61,15.88 35.24,16.51 IC17.14 | v18.73,55.56 20.32,57.15 U2.24
A15  (via drill 0.61)
  Top 0.406: v40.64,6.35 40.64,6.67 38.42,8.89 IC17.4 | v70.48,5.08 72.71,7.3 72.71,10.79 71.75,11.75 71.75,16.51 72.39,17.14 72.39,18.41 73.66,19.68 IC1.9 73.66,32.07 74.93,33.34 74.93,46.99 80.01,52.07 80.01,83.5 v80.33,83.82 | v83.5,84.45 83.5,86.68 85.09,88.27 85.09,101.92 86.04,102.87 JP2.14
  Bottom 0.406: v40.64,6.35 41.91,5.08 50.16,5.08 50.8,5.71 68.26,5.71 68.9,5.08 v70.48,5.08 | v83.5,84.45 82.87,83.82 v80.33,83.82
A15'  (via drill 0.61)
  Top 0.406: v31.75,13.65 31.75,12.38 32.7,11.43 IC17.2 | v5.08,14.29 3.17,16.19 3.17,46.67 v6.35,49.85
  Bottom 0.406: v31.75,13.65 31.11,14.29 v5.08,14.29 | v6.35,49.85 14.92,58.42 28.57,58.42 29.84,59.69 U2.25
D0  (via drill 0.61)
  Top 0.406: v52.07,78.74 v54.93,75.88 | JP4.14 86.04,97.79 85.72,97.47 85.72,75.88 86.36,75.25 IC4.11
  Bottom 0.406: IC8.6 IC4.11 74.93,74.93 73.66,76.2 67.31,76.2 66.04,74.93 IC26.11 63.82,75.56 55.24,75.56 v54.93,75.88 | v52.07,78.74 48.58,78.74 47.94,78.11 44.77,78.11 44.45,77.79 IC7.9
D0'
  Bottom 0.406: U2.33 IC7.11
D1  (via drill 0.61)
  Top 0.406: v57.15,76.52 v59.05,78.42 | JP2.15 89.22,102.87 90.17,101.92 90.17,79.06 88.9,77.79 IC4.12
  Bottom 0.406: IC8.5 IC4.12 74.93,77.47 73.66,78.74 67.31,78.74 66.04,77.47 IC26.12 63.82,78.11 59.37,78.11 v59.05,78.42 | v57.15,76.52 56.83,76.83 51.12,76.83 50.48,76.2 45.4,76.2 44.45,75.25 IC7.8
D1'
  Bottom 0.406: U2.32 IC7.12
D2
  Top 0.406: JP4.15 89.22,97.79 89.53,97.47 89.53,80.96 88.9,80.33 IC4.13
  Bottom 0.406: IC8.4 IC4.13 74.93,80.01 73.66,81.28 67.31,81.28 66.04,80.01 IC26.13 63.18,80.01 61.91,81.28 46.67,81.28 44.13,78.74 40.32,78.74 40.32,74.93 42.23,73.03 IC7.7
D2'
  Bottom 0.406: U2.31 IC7.13
D3  (via drill 0.61)
  Top 0.406: v47.94,71.12 47.62,71.44 47.62,81.6 48.26,82.23 IC26.15 | JP2.16 91.76,102.87 92.71,101.92 92.71,89.53 92.08,88.9 92.08,83.5 92.71,82.87 IC8.3
  Bottom 0.406: IC26.15 62.23,82.55 63.5,81.28 66.04,81.28 67.31,82.55 IC4.15 73.66,82.55 74.93,81.28 88.9,81.28 90.17,82.55 IC8.3 | v47.94,71.12 45.4,71.12 44.45,70.17 IC7.6
D3'
  Bottom 0.406: U2.30 IC7.14
D4  (via drill 0.61)
  Top 0.406: v46.04,79.06 46.04,69.22 44.45,67.63 IC7.5 | 99.69,81.6 99.69,67.31 100.33,66.67 100.33,36.51 101.28,35.56 IC13.12 | 99.69,81.6 100.33,82.23 IC8.14 | v97.79,92.39 99.69,90.49 99.69,81.6
  Bottom 0.406: v46.04,79.06 46.99,80.01 IC26.16 62.23,80.01 63.5,78.74 66.04,78.74 67.31,80.01 IC4.16 73.66,79.69 74.61,78.74 94.93,78.74 98.74,82.55 IC8.14 | v97.79,92.39 97.16,92.39 91.76,97.79 JP4.16
D4'
  Bottom 0.406: U2.29 IC7.15
D5  (via drill 0.61)
  Top 0.406: v41.27,75.88 41.27,65.72 41.91,65.09 IC7.4 | v85.41,36.2 83.82,37.78 v83.82,76.2 | JP2.17 94.61,103.19 96.52,101.28 103.19,101.28 103.19,88.27 103.5,87.95 103.5,80.96 102.87,80.33 IC8.13
  Bottom 0.406: IC8.13 99.69,80.01 95.89,76.2 v83.82,76.2 74.93,76.2 73.66,77.47 IC4.17 67.31,77.47 66.04,76.2 63.5,76.2 62.23,77.47 IC26.17 45.4,77.47 44.13,76.2 41.59,76.2 v41.27,75.88 | v85.41,36.2 107.63,36.2 108.58,35.24 IC13.9
D5'
  Bottom 0.406: U2.28 IC7.16
D6  (via drill 0.61)
  Top 0.406: v105.73,75.88 106.36,75.88 115.57,66.67 115.57,49.85 114.94,49.21 114.94,35.56 114.3,34.92 114.3,33.66 111.76,31.11 111.76,23.5 100.01,23.5 97.79,25.72 97.79,27.62 98.42,28.26 98.42,28.57 99.06,28.57 101.92,31.43 101.92,32.38 105.41,32.38 105.73,32.07 105.73,28.57 106.36,27.94 IC13.7 | v98.74,77.15 98.74,85.72 94.61,89.85 94.61,97.47 94.3,97.79 JP4.17
  Bottom 0.406: 99.06,76.83 95.89,73.66 74.93,73.66 73.66,74.93 IC4.18 67.31,74.93 66.04,73.66 63.5,73.66 62.23,74.93 IC26.18 47.94,74.93 44.13,71.12 41.27,71.12 41.27,63.82 42.23,62.87 IC7.3 | 99.06,76.83 99.69,77.47 IC8.12 104.14,77.47 v105.73,75.88 | 99.06,76.83 v98.74,77.15
D6'
  Bottom 0.406: U2.27 IC7.17
D7  (via drill 0.61)
  Top 0.406: v53.02,60.96 52.7,61.28 52.7,69.53 50.48,71.75 IC26.19 | v105.73,74.61 105.73,73.98 113.03,66.67 113.03,57.78 113.35,57.47 113.35,46.67 111.76,45.09 111.76,32.7 111.12,32.07 111.12,24.13 101.28,24.13 99.69,25.72 IC13.4 | JP2.18 97.16,103.19 103.82,103.19 103.82,88.58 104.14,88.27 104.14,76.52 102.87,75.25 IC8.11
  Bottom 0.406: IC26.19 62.23,72.39 63.5,71.12 66.04,71.12 67.31,72.39 IC4.19 73.66,72.39 74.93,71.12 95.89,71.12 99.69,74.93 IC8.11 105.41,74.93 v105.73,74.61 | v53.02,60.96 45.4,60.96 44.45,60.01 IC7.2
D7'
  Bottom 0.406: U2.26 IC7.18
GND  (via drill 0.61)
  Top 0.813: JP4.18 CD15.1 | JP1.2 R11.1 | JP3.2 R41.2 133.35,98.42 138.75,93.03 138.75,84.45 139.06,84.14 139.06,74.61 136.53,72.07 133.35,72.07 C5.2 | VIDEO_OUT.2 R9.2 | RESET.1 C7.2 39.37,96.2 41.27,94.3 41.27,81.6 42.23,80.64 IC7.10 | v68.9,84.14 68.9,55.24 ROMSEL.3 | v96.2,82.23 96.2,71.12 95.25,70.17 IC8.8 | U2.1 15.24,98.42 10.79,102.87 10.79,103.19 PWR.2 | U2.21 33.02,48.9 IC16.15 v33.02,30.8 | v10.16,30.8 IC9.15 9.84,35.56 9.84,44.13 10.16,44.45 10.16,47.62 9.84,47.94 9.84,74.93 12.7,77.79 CD5.1 | v25.72,29.53 25.72,27.94 IC9.8 | v47.94,30.48 47.94,27.94 IC16.8 | v54.61,30.8 CD11.1 | IC18.7 68.26,8.89 68.26,5.71 70.17,3.81 73.66,3.81 CD3.1 | IC17.3 35.24,11.43 33.02,13.65 IC17.15 | IC22.8 151.45,50.8 153.03,52.39 153.03,58.74 151.13,60.64 IC2.7 | IC1.10 IC1.11 76.2,37.15 77.47,38.42 CD1.1 | v107.31,29.53 108.9,27.94 IC13.8 | CD13.1 107.95,10.79 105.09,7.94 95.57,7.94 94.3,9.21 94.3,9.53 R4.1 | CD14.1 133.35,15.56 131.76,17.14 131.76,27.3 133.03,28.57 CD2.1 133.35,30.8 127.32,36.83 127.32,44.77 130.81,48.26 CD9.1 | v80.01,30.8 R28.1
  Bottom 0.813: 120.65,106.36 116.52,106.36 115.57,105.41 VIDEO_OUT.2 | 120.65,106.36 121.28,106.36 | R9.2 R6.1 113.35,99.69 111.76,98.11 97.16,98.11 JP4.18 | 130.49,106.36 132.08,106.36 | 130.49,106.36 123.19,106.36 | 123.19,106.36 121.92,106.36 | 121.92,106.36 121.6,106.36 | 133.35,106.36 132.4,106.36 | JP1.2 148.59,105.41 147.32,106.36 133.35,106.36 | IC8.8 95.25,70.17 97.47,70.17 99.69,72.39 IC8.10 | 68.9,84.45 78.11,84.45 80.01,82.55 IC4.14 88.9,82.87 89.85,83.82 96.2,83.82 | 68.9,84.45 67.63,84.45 66.04,82.87 IC26.14 63.5,82.87 61.91,84.45 47.94,84.45 44.13,80.64 IC7.10 | 97.47,83.82 96.2,83.82 | 97.47,83.82 99.38,83.82 100.33,84.77 IC8.15 | 68.9,84.45 v68.9,84.14 | 96.2,83.82 v96.2,82.23 | CD15.1 94.61,90.81 91.76,87.95 91.76,86.36 95.25,86.36 97.47,84.14 97.47,83.82 | PWR.2 9.84,102.87 5.4,98.42 D14.A 6.99,97.79 6.99,86.04 12.38,80.64 CD5.1 | CD7.1 8.57,29.21 v10.16,30.8 11.43,29.53 v25.72,29.53 26.04,29.53 26.35,29.21 CD12.1 29.53,29.21 31.11,30.8 v33.02,30.8 47.62,30.8 v47.94,30.48 48.26,30.8 v54.61,30.8 54.93,30.48 67.94,30.48 68.26,30.8 v80.01,30.8 85.72,30.8 87.31,29.21 CD4.1 89.53,29.53 v107.31,29.53 113.03,29.53 113.35,29.21 CD2.1 | IC10.15 9.84,16.51 8.89,15.56 4.76,15.56 3.81,14.61 3.81,12.7 CD6.1 25.72,12.7 | 48.58,12.38 48.58,12.7 CD10.1 51.44,13.02 69.85,13.02 70.17,12.7 CD3.1 74.3,13.02 105.73,13.02 106.05,12.7 CD13.1 108.58,13.02 131.13,13.02 131.44,12.7 CD14.1 133.99,13.02 149.22,13.02 150.81,11.43 IC21.7 | 48.58,12.38 48.58,11.43 IC17.8 | 25.72,12.7 25.72,11.43 IC10.8 | 25.72,12.7 CD8.1 28.57,12.38 34.29,12.38 | 34.29,12.38 35.24,11.43 IC17.3
  Bottom 0.813: 34.29,12.38 48.58,12.38 | C4.2 C5.2 133.99,66.99 134.62,66.36 147.96,66.36 150.81,63.5 IC2.7 | CD9.1 131.44,52.39 149.22,52.39 150.81,50.8 IC22.8 | R28.1 IC1.11 | R4.1 IC19.7 | IC20.8 128.91,9.21 130.81,7.3 149.22,7.3 150.81,8.89 IC21.7 | IC14.7 151.45,25.4 153.99,22.86 153.99,10.16 IC21.7 | 123.19,106.36 ZV.2 | 121.92,106.36 120.65,106.36 | 133.35,106.36 130.49,106.36 | JP3.2 133.35,106.36
HBORDER  (via drill 0.61)
  Top 0.406: IC20.15 v113.03,20.64 D8.C
  Bottom 0.406: v113.03,20.64 146.05,20.64 147.96,18.73 IC21.9
HSYNC
  Top 0.406: IC20.11 D10.C
I/O  (via drill 0.61)
  Top 0.406: v67.94,38.73 67.94,37.15 66.36,35.56 IC1.15 | v84.77,39.37 v84.77,86.36 | v56.2,95.89 55.88,96.2 JP4.2
  Bottom 0.406: v67.94,38.73 68.58,39.37 v84.77,39.37 | v84.77,86.36 75.25,95.89 v56.2,95.89
IRQ  (via drill 0.61)
  Top 0.406: v58.42,94.93 JP4.3 | R33.2 13.34,87.95 14.92,89.53 14.92,89.85 U2.4
  Bottom 0.406: v58.42,94.93 54.93,91.44 19.05,91.44 18.1,90.49 U2.4
N$1
  Top 0.406: T3.1 R45.1
N$2
  Bottom 0.406: IC3.16 D15.A
N$3
  Bottom 0.406: ROMSEL.2 IC4.27
N$4
  Top 0.406: R45.2 VIDEO_OUT.1
N$5
  Top 0.406: IC14.8 D1.C
N$7
  Top 0.406: IC20.7 126.36,9.21 127.32,8.26 136.53,8.26 136.53,8.57 137.16,9.21 137.16,11.11 142.24,16.19 142.24,18.73 142.88,19.37 142.88,21.27 147.32,25.72 147.32,27.62 148.59,28.89 IC14.9
N$8
  Top 0.406: D3.A 118.11,28.57 116.84,27.3 116.84,26.04 116.2,25.4 116.2,18.73 IC20.14
  Bottom 0.406: D3.A 118.43,34.92 119.38,35.88 124.46,35.88 125.41,34.92 D2.A | IC20.14 115.25,16.51 114.62,15.88 106.36,15.88 104.78,17.46 R2.2
N$9  (via drill 0.61)
  Top 0.406: IC18.2 56.2,11.43 58.42,13.65 IC18.12 v58.42,21.91 | v50.8,23.81 D4.A | IC19.12 81.28,13.65 79.06,11.43 IC19.2 78.74,1.91 145.1,1.91 152.72,9.53 152.72,39.37 151.13,40.96 D1.A
  Bottom 0.406: v50.8,23.81 53.02,21.59 58.1,21.59 v58.42,21.91 | IC19.2 78.11,11.11 77.15,12.06 75.56,12.06 74.3,10.79 72.07,10.79 71.75,10.48 R3.2 70.8,10.79 69.53,12.06 56.83,12.06 56.2,11.43 IC18.2
N$14
  Top 0.406: C2.1 JP1.3
N$15
  Top 0.406: IC21.2 138.11,8.89 135.57,6.35 85.09,6.35 85.09,7.94 86.04,8.89 IC19.5 | R4.2 93.98,14.29 96.52,11.75 D5.C
  Bottom 0.406: IC19.5 86.68,11.43 87.31,12.06 94.93,12.06 96.2,10.79 D5.C
N$17  (via drill 0.61)
  Top 0.406: v77.79,4.76 77.79,1.59 67.94,1.59 65.72,3.81 65.72,8.26 64.77,9.21 64.77,19.68 63.18,19.68 62.23,18.73 62.23,16.83 61.59,16.19 61.59,11.75 61.28,11.43 IC18.4 | v82.23,7.3 83.82,5.71 139.7,5.71 139.7,11.11 141.92,13.34 v141.92,14.29
  Bottom 0.406: v77.79,4.76 80.33,7.3 v82.23,7.3 | v141.92,14.29 141.92,16.51 141.29,16.51 IC21.12
N$18
  Top 0.406: IC20.2 112.71,11.43 109.22,14.92 109.22,18.41 108.27,19.37 101.6,19.37 R22.1
  Bottom 0.406: D5.A D13.A R22.1
N$20  (via drill 0.61)
  Top 0.406: IC14.5 145.73,27.94 144.78,28.89 144.78,35.24 146.05,36.51 IC22.6 146.05,54.93 147.32,56.2 147.32,63.18 v145.41,65.09
  Bottom 0.406: v145.41,65.09 123.83,65.09 123.83,81.28 120.97,84.14 114.3,84.14 113.67,84.77 C1.1
N$21
  Top 0.406: R6.2 C1.2
  Bottom 0.406: IC8.1 95.25,87.95 96.2,88.9 104.78,88.9 108.58,92.71 R5.1 R6.2
N$22
  Top 0.406: IC21.4 143.83,11.43 146.05,13.65 IC21.10 | IC21.13 138.43,13.65 136.21,11.43 IC21.1 135.25,10.79 133.35,10.79 130.81,13.34 130.81,32.07 126.36,36.51 126.36,69.53 127.32,70.48 127.32,85.72 127,86.04 127,86.68 127.32,87 127.32,93.98 123.19,98.11 R26.2
  Bottom 0.406: IC21.4 143.19,8.89 142.56,8.26 136.84,8.26 136.21,8.89 IC21.1
N$23
  Bottom 0.406: IC8.9 102.87,70.17 114.94,82.23 D6.C
N$24
  Top 0.406: R7.1 118.11,67.63 118.43,67.31 118.43,47.62 115.57,44.77 D7.A
  Bottom 0.406: R7.1 D6.A | D8.A D7.A
N$26  (2 unrouted)
  Top 0.406: R7.2 118.11,77.79 120.33,75.56 R8.1 D9.A
  Bottom 0.406: D9.A D10.A | 115.89,86.36 115.89,92.08 R9.1
N$27
  Top 0.406: R14.2 R13.2 151.13,84.14 148.59,86.68 D12.C
  Bottom 0.406: D12.C D11.A | R15.1 R14.2
N$28
  Top 0.406: R10.2 144.15,90.49 145.73,92.08 C2.2
  Bottom 0.406: C2.2 R11.2
N$29
  Top 0.406: IC22.13 141.29,58.42 142.24,59.37 142.24,70.8 141.6,71.44 141.6,81.28 142.88,82.55 R10.1
  Bottom 0.406: R29.2 126.36,75.25 131.76,80.64 139.7,80.64 141.6,82.55 R10.1
N$30
  Top 0.406: R29.1 T1.2
N$31
  Top 0.406: T1.1 R12.1
N$32
  Top 0.406: R12.2 ZV.1
N$33
  Top 0.406: R18.2 JP1.5
N$34
  Top 0.406: R13.1 C3.1
N$37
  Bottom 0.406: IC3.15 D16.A
N$38
  Top 0.406: JP1.1 C3.2
N$39
  Bottom 0.406: IC2.8 150.5,70.8 149.54,71.75 148.91,71.75 R15.2 R16.1
N$40
  Top 0.406: R16.2 146.69,80.33 148.27,81.92 D12.A
N$41
  Top 0.406: R14.1 150.5,72.71 149.22,73.98 143.51,73.98 R17.2
  Bottom 0.406: IC2.12 141.29,71.12 141.29,72.39 R17.2
N$42
  Top 0.406: R17.1 144.15,80.33 145.73,81.92 D11.C
N$43  (via drill 0.61)
  Top 0.406: v104.78,31.43 104.78,28.26 104.46,27.94 IC13.6 | v153.67,31.75 153.99,32.07 153.99,62.55 148.59,67.94 IC2.9
  Bottom 0.406: v104.78,31.43 105.09,31.75 v153.67,31.75
N$44
  Top 0.406: R42.1 JP3.1
N$46  (via drill 0.61)
  Top 0.406: v100.97,32.07 96.84,27.94 IC13.3 | v144.78,37.47 145.41,38.1 145.41,47.94 144.78,48.58 144.78,58.1 146.05,59.37 IC2.5
  Bottom 0.406: v100.97,32.07 101.28,32.38 128.27,32.38 132.08,36.2 143.51,36.2 v144.78,37.47
N$47
  Top 0.406: IC2.3 140.34,61.28 139.38,60.33 130.81,60.33 C4.1
N$48
  Top 0.406: R19.1 143.19,92.08 140.02,88.9 140.02,71.12 139.7,70.8 139.7,68.9 138.43,67.63 IC2.2
  Bottom 0.406: C5.1 IC2.1 IC2.2
N$49
  Top 0.406: R19.2 JP1.4
N$50
  Top 0.406: IC14.13 138.43,40.01 Q1.1
  Bottom 0.406: R20.2 133.99,38.42 136.21,40.64 Q1.1
N$51
  Top 0.406: IC14.4 143.19,27.94 142.24,28.89 142.24,38.42 140.65,40.01 140.65,47.62 139.7,48.58 139.7,53.98 138.43,55.24 IC22.14
N$52
  Top 0.406: IC14.11 143.83,35.56 143.83,38.1 144.78,39.05 144.78,42.55 143.51,43.81 C6.2
  Bottom 0.406: C6.2 R21.1
N$53
  Top 0.406: IC14.12 140.65,35.56 140.02,36.2 140.02,42.23 138.43,43.81 C6.1
  Bottom 0.406: C6.1 R20.1
N$54
  Bottom 0.406: R23.2 12.38,90.81 10.79,92.39 10.79,96.52 26.04,96.52 29.84,92.71 U2.38
N$55
  Bottom 0.406: IC3.14 D17.A
N$56
  Bottom 0.406: IC3.13 D18.A
N$62
  Top 0.406: IC18.10 63.18,16.51 62.23,15.56 62.23,9.21 60.64,7.62 60.64,4.13 60.33,3.81 21.59,3.81 21.59,23.5 20.32,24.77 IC9.6
N$64
  Bottom 0.406: IC3.12 D19.A
N$70
  Top 0.406: IC13.11 103.82,35.56 102.87,36.51 102.87,38.73 104.14,40.01 R36.2
  Bottom 0.406: R36.2 IC3.5
N$71
  Top 0.406: IC13.14 96.2,35.56 95.25,36.51 95.25,38.73 96.52,40.01 R38.2
  Bottom 0.406: R38.2 IC3.2
N$72
  Top 0.406: IC13.10 107,35.56 108.27,36.83 108.27,42.23 106.68,43.81 R37.2
  Bottom 0.406: R37.2 IC3.6
N$73
  Top 0.406: IC13.5 102.23,25.72 103.19,24.77 110.49,24.77 110.49,32.38 110.81,32.7 110.81,44.45 107.95,47.31 107.95,49.21 107,50.16 101.6,50.16 IC3.4
  Bottom 0.406: IC3.4 R35.2
N$74  (via drill 0.61)
  Top 0.406: IC13.2 93.66,27.94 92.71,28.89 92.71,42.55 93.98,43.81 R34.2 | v128.59,58.42 128.59,68.26 130.81,70.48 R43.1
  Bottom 0.406: R34.2 IC3.1 94.3,49.53 95.89,51.12 121.28,51.12 v128.59,58.42
N$75
  Top 0.406: IC13.13 98.74,35.56 97.79,36.51 97.79,38.73 99.06,40.01 R39.2
  Bottom 0.406: R39.2 IC3.3
N$76
  Bottom 0.406: IC22.2 136.21,50.8 136.84,51.44 147,51.44 147.96,50.48 IC22.7
N$77
  Bottom 0.406: IC22.3 IC22.4
N$78
  Bottom 0.406: IC22.11 146.37,58.42 148.27,60.33 151.45,60.33 152.72,61.59 152.72,74.93 R44.1 R40.1
N$79
  Top 0.406: R40.2 T2.2
N$80
  Top 0.406: T2.3 R41.1
  Bottom 0.406: R41.1 R42.2
N$81
  Top 0.406: R43.2 JP3.3
N$82
  Bottom 0.406: IC3.11 D20.A
N$83
  Bottom 0.406: IC3.10 D21.A
N$84
  Bottom 0.406: IC3.9 D22.A
N$85
  Bottom 0.406: IC3.8 112.39,49.21 120.65,49.21 128.91,57.47 129.22,57.47 129.54,57.78 129.54,59.37 119.38,59.37 118.43,58.42 D23.A
N$86  (via drill 0.61)
  Top 0.406: v114.3,50.16 D24.A
  Bottom 0.406: v114.3,50.16 110.17,50.16 109.54,49.53 IC3.7
NMI
  Bottom 0.406: U2.6 R31.2 9.53,85.09 9.53,97.47 19.05,107 58.42,107 60.33,105.09 JP2.4
PHI0  (via drill 0.61)
  Top 0.406: IC21.3 141.29,11.43 143.51,13.65 IC21.11 143.51,20.64 148.27,25.4 IC14.6 | v42.86,83.82 46.99,79.69 46.99,25.72 48.26,24.45 48.26,20 49.53,18.73 49.53,17.14 v50.48,16.19
  Bottom 0.406: IC14.1 136.21,25.4 136.84,24.77 147.64,24.77 148.27,25.4 IC14.6 | IC21.11 142.88,18.73 141.92,19.68 132.4,19.68 127.95,15.24 57.47,15.24 56.2,16.51 IC18.13 55.56,16.51 55.24,16.51 54.61,15.88 50.8,15.88 v50.48,16.19 | v42.86,83.82 39.37,83.82 33.34,89.85 U2.37
PHI0'  (via drill 0.61)
  Top 0.406: IC17.1 30.8,11.43 30.8,15.88 31.75,16.83 31.75,22.23 30.48,23.5 IC16.1 | IC10.1 7.3,11.43 6.67,12.06 6.67,16.51 6.35,16.83 6.35,18.73 7.62,20 IC9.1 | v64.77,94.93 64.77,101.92 65.72,102.87 JP2.6
  Bottom 0.406: IC14.2 137.79,27.62 136.84,28.57 135.25,28.57 133.99,27.3 127.95,27.3 127,28.26 109.86,28.26 109.54,28.57 90.81,28.57 89.53,27.3 84.14,27.3 82.87,28.57 54.29,28.57 53.66,27.94 IC1.1 52.7,27.62 51.75,28.57 31.43,28.57 30.8,27.94 IC16.1 29.84,27.3 26.99,27.3 25.72,28.57 9.21,28.57 8.57,27.94 7.94,27.94 IC9.1 | IC10.1 2.54,10.16 2.54,60.01 8.57,66.04 18.1,66.04 23.18,60.96 33.34,60.96 34.29,60.01 IC7.19 37.47,59.69 37.47,76.83 51.44,90.81 60.64,90.81 v64.77,94.93
PHI2
  Top 0.406: IC1.2 56.2,27.94 57.15,28.89 57.15,37.47 55.56,39.05 55.56,44.13 56.2,44.77 56.2,57.15 55.88,57.47 55.88,94.61 53.34,97.16 JP4.1
  Bottom 0.406: U2.39 33.34,95.57 33.66,95.89 42.55,95.89 45.72,99.06 JP4.1
R/W  (via drill 0.61)
  Top 0.406: v71.75,40.32 71.75,37.15 73.34,35.56 IC1.12 | v61.28,40.64 v61.28,50.8 60.96,51.12 60.96,61.91 62.55,63.5 62.55,83.5 63.18,84.14 63.18,97.79 JP4.5
  Bottom 0.406: IC7.1 44.13,56.52 44.13,52.07 IC26.27 60.01,52.07 v61.28,50.8 | v71.75,40.32 71.44,40.64 v61.28,40.64
R/WB  (via drill 0.61)
  Top 0.406: v52.07,47.31 52.07,25.72 53.02,24.77 53.02,22.86 55.56,22.86 58.1,25.4 IC1.3 | v38.42,47.62 37.78,48.26 37.78,80.01 35.56,82.23 33.34,82.23 U2.34
  Bottom 0.406: v52.07,47.31 51.75,47.62 v38.42,47.62
RAMCS\  (via drill 0.61)
  Top 0.406: IC26.22 48.26,65.09 47.62,65.72 47.62,68.9 48.26,69.53 IC26.20 50.48,69.22 52.07,67.63 52.07,60.33 53.02,59.37 53.02,46.67 52.7,46.35 52.7,43.5 v53.34,42.86 | v70.8,42.55 70.8,35.56 IC1.13
  Bottom 0.406: v70.8,42.55 70.48,42.86 v53.34,42.86
RDY
  Bottom 0.406: JP2.3 57.78,105.09 56.52,106.36 19.37,106.36 10.16,97.16 10.16,88.9 13.34,88.9 14.29,89.85 14.29,92.71 R32.2 13.34,93.03 13.65,93.03 15.24,94.61 U2.2
ROMCS\
  Top 0.406: IC1.14 68.9,35.56 68.9,46.04 69.22,46.35 71.12,46.35 71.12,45.72 72.39,44.45 74.3,44.45 74.3,63.18 73.34,64.14 IC4.22 71.12,65.09 70.48,65.72 70.48,68.9 71.12,69.53 IC4.20
RST
  Top 0.406: R25.1 D14.C | C7.1 RESET.2
  Bottom 0.406: C7.1 U2.40 29.84,97.79 28.26,99.38 14.61,99.38 13.34,98.11 D14.C | JP4.4 60.33,100.01 58.42,101.92 38.1,101.92 37.15,102.87 RESET.2
SYNC
  Top 0.406: JP2.5 62.87,105.09 60.64,107.31 18.73,107.31 18.73,84.14 17.78,83.19 U2.7
  Bottom 0.406: R24.2 U2.7
VBORDER
  Top 0.406: IC20.1 111.12,9.21 112.08,8.26 114.3,8.26 114.3,18.73 115.57,20 D7.C
  Bottom 0.406: IC21.6 147.96,11.11 147,12.06 135.25,12.06 133.99,10.79 130.49,10.79 129.22,12.06 111.44,12.06 110.81,11.43 IC20.1
VCC  (via drill 0.61)
  Top 0.813: CD13.2 107.63,17.14 104.14,13.65 R2.1 | IC21.14 135.57,19.05 133.99,20.64 133.99,27.3 135.89,29.21 IC14.14 136.21,35.56 136.21,47.31 137.16,48.26 137.16,58.42 136.21,59.37 133.35,59.37 IC22.16 | v113.03,14.29 110.81,16.51 IC20.16 | IC2.4 143.83,63.5 144.15,63.82 144.15,66.04 146.05,67.94 IC2.10 | T2.1 135.89,85.41 137.16,84.14 R44.2 | CD15.2 IC8.16 | R8.2 T3.3 120.65,87.95 123.19,90.49 R26.1 123.19,94.61 116.52,94.61 111.12,100.01 R5.2 | CD9.2 127.32,57.15 127.32,69.22 128.27,70.17 T1.3 | v49.85,36.83 49.53,37.15 CD11.2 IC26.28 | v35.56,53.66 IC7.20 | IC4.28 CD1.2 | v82.55,49.21 R27.2 | CD4.2 88.9,46.35 87.63,47.62 IC4.1 | v91.76,38.1 91.44,37.78 IC13.16 | PWR.1 7.3,102.87 6.99,102.55 6.99,96.2 5.71,94.93 R25.2 R32.1 R23.1 R33.1 R31.1 R24.1 5.08,80.33 6.99,80.33 CD5.2 IC9.16 7.62,29.21 5.4,26.99 5.4,18.41 CD6.2 | JP2.1 52.7,105.09 40.96,105.09 40.96,105.73 40.32,106.36 19.68,106.36 19.68,81.92 18.1,80.33 U2.8 | 28.57,20.64 30.16,19.05 IC17.16 | 28.57,20.64 28.57,27.3 30.48,29.21 IC16.16 30.48,46.67 v31.75,47.94 | v41.91,13.65 43.18,12.38 IC17.6 | v50.8,20.64 CD10.2 | v71.12,20.64 R3.1 | v38.1,20.64 IC17.13 | v28.26,20.64 28.57,20.64 | v129.22,38.1 132.72,34.61 CD2.2
  Bottom 0.813: IC20.16 CD13.2 | R2.1 R22.2 | IC21.14 CD14.2 131.76,17.78 128.27,14.29 v113.03,14.29 | CD2.2 IC14.14 | CD9.2 IC22.16 133.67,58.42 135.25,60.01 142.24,60.01 143.19,60.96 IC2.4 | IC2.14 136.21,68.58 137.16,67.63 144.78,67.63 145.73,68.58 IC2.10 | R18.1 140.65,92.08 136.53,87.95 136.21,87.95 T2.1 135.89,87 134.62,85.72 130.49,85.72 129.86,86.36 T1.3 128.27,85.72 127,84.45 124.14,84.45 122.24,86.36 T3.3 | CD15.2 102.23,91.12 105.73,94.61 119.7,94.61 121.6,92.71 R26.1 | v49.85,36.83 51.75,36.83 53.02,35.56 IC1.20 | 37.31,51.91 39.69,49.53 IC26.28 | 37.31,51.91 v35.56,53.66 | CD4.2 IC13.16 | 82.55,49.53 IC4.1 | 82.55,49.53 IC4.28 ROMSEL.1 67.31,49.85 66.99,49.85 66.04,50.8 63.5,50.8 62.23,49.53 60.01,49.53 55.24,44.77 53.98,44.77 53.02,45.72 50.48,45.72 50.16,46.04 CD11.2 | 82.55,49.53 v82.55,49.21 | v91.76,38.1 R34.1 R38.1 R39.1 R35.1 R36.1 R37.1 v129.22,38.1 | CD5.2 8.26,79.69 10.16,77.79 12.7,77.79 14.61,79.69 14.92,79.69 U2.8 | IC17.16 CD8.2 | IC16.16 CD12.2 | v41.91,13.65 39.69,15.88 39.05,15.88 38.42,16.51 IC17.13 | IC19.14 CD3.2 R3.1 | CD10.2 IC18.14 | CD6.2 IC10.16 7.94,19.05 9.53,20.64 v28.26,20.64 v38.1,20.64 v50.8,20.64 v71.12,20.64 | IC9.16 CD7.2 | v31.75,47.94 33.34,47.94 37.15,51.75 37.31,51.91
VSYNC
  Top 0.406: IC20.5 120.33,11.43 119.38,12.38 119.38,18.73 120.65,20 D9.C

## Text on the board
Top: ORAO 2007
Bottom: ORAO 2007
